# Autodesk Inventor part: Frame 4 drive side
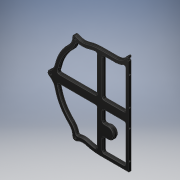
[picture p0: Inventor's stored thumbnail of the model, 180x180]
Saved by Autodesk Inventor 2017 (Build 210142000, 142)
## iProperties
Created: 2016-06
Part Number: Frame 4 drive side
Material: Generic
Document SubType Name: Modeling
Designer: Stan
Density: 1 g/cm^3
Appearance: Glossy - Black
Author: Stan
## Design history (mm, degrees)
sketch "Sketch1"
  geometry: L1 (9.525, 88.9)-(33.07, 88.9); L2 (0, -98.425)-(60.566, -98.425); L3 (9.525, -88.9)-(51.041, -88.9); L4 (6.35, 85.725)-(6.35, 12.7); L5 (6.35, -63.063)-(6.35, -85.725); L6 (-6.35, 85.194)-(-6.35, 12.7); L7 (-6.35, -12.7)-(-6.35, -85.194); L8 (-85.613, -9.525)-(-9.525, -9.525); L9 (9.525, -9.525)-(51.041, -9.525); L10 (-85.613, 9.525)-(-9.525, 9.525); L11 (9.525, 9.525)-(51.041, 9.525); L12 (33.07, 98.425)-(0, 98.425); L13 (60.566, 114.3)-(60.566, 110.49); L14 (60.566, 105.41)-(60.566, -98.425); L15 (54.216, 90.23)-(54.216, 12.7); L16 (54.216, -12.7)-(54.216, -85.725); L17 (6.35, -31.313)-(6.35, -12.7); L18 (17.394, -34.488)-(9.525, -34.488); L19 (17.394, -59.888)-(9.525, -59.888); C1 r 3.175 at (0, 0); C2 r 2.54 at (-104.775, 0); C3 r 2.54 at (-52.387, -90.738); C4 r 2.54 at (-52.388, 90.738); C5 r 3.175 at (17.394, -47.188); A1 r 3.175 centre (9.525, -85.725) between (6.35, -85.725) and (9.525, -88.9); A2 r 3.175 centre (9.525, 85.725) between (9.525, 88.9) and (6.35, 85.725); A3 r 3.175 centre (-9.525, -12.7) between (-6.35, -12.7) and (-9.525, -9.525); A4 r 3.175 centre (9.525, -12.7) between (9.525, -9.525) and (6.35, -12.7); A5 r 3.175 centre (51.041, -12.7) between (54.216, -12.7) and (51.041, -9.525); A6 r 3.175 centre (-9.525, 12.7) between (-9.525, 9.525) and (-6.35, 12.7); A7 r 3.175 centre (9.525, 12.7) between (6.35, 12.7) and (9.525, 9.525); A8 r 3.175 centre (51.041, 12.7) between (51.041, 9.525) and (54.216, 12.7); A9 r 98.425 centre (0, 0) between (0, 98.425) and (-29.099, 94.025); A10 r 98.425 centre (0, 0) between (-66.878, 72.213) and (-95.978, 21.812); A11 r 98.425 centre (0, 0) between (-95.978, -21.812) and (-66.878, -72.213); A12 r 98.425 centre (0, 0) between (-29.099, -94.025) and (0, -98.425); A13 r 88.9 centre (0, 0) between (-9.878, 88.35) and (-26.283, 84.926); A14 r 3.175 centre (-9.525, 85.194) between (-6.35, 85.194) and (-9.878, 88.35); A15 r 88.9 centre (0, 0) between (-60.406, 65.225) and (-86.69, 19.701); A16 r 88.9 centre (0, 0) between (-86.69, -19.701) and (-60.406, -65.225); A17 r 88.9 centre (0, 0) between (-26.283, -84.926) and (-9.878, -88.35); A18 r 3.175 centre (-9.525, -85.194) between (-9.878, -88.35) and (-6.35, -85.194); A19 r 6.35 centre (-104.775, 0) between (-107.969, 5.488) and (-107.969, -5.488); A20 r 25.4 centre (-120.746, 27.441) between (-107.969, 5.488) and (-95.978, 21.812); A21 r 34.925 centre (-120.746, 27.441) between (-88.541, 13.928) and (-86.69, 19.701); A22 r 3.175 centre (-85.613, 12.7) between (-88.541, 13.928) and (-85.613, 9.525); A23 r 25.4 centre (-120.746, -27.441) between (-95.978, -21.812) and (-107.969, -5.488); A24 r 34.925 centre (-120.746, -27.441) between (-86.69, -19.701) and (-88.541, -13.928); A25 r 3.175 centre (-85.613, -12.7) between (-85.613, -9.525) and (-88.541, -13.928); A26 r 6.35 centre (-52.387, -90.738) between (-58.737, -90.76) and (-49.232, -96.248); A27 r 25.4 centre (-84.137, -90.849) between (-58.737, -90.76) and (-66.878, -72.213); A28 r 34.925 centre (-84.137, -90.849) between (-50.239, -82.443) and (-60.406, -65.225); A29 r 3.175 centre (-47.157, -81.679) between (-50.239, -82.443) and (-46.278, -84.73); A30 r 25.4 centre (-36.609, -118.29) between (-29.099, -94.025) and (-49.232, -96.248); A31 r 34.925 centre (-36.609, -118.29) between (-26.283, -84.926) and (-46.278, -84.73); A32 r 6.35 centre (-52.388, 90.738) between (-49.232, 96.248) and (-58.737, 90.76); A33 r 25.4 centre (-36.609, 118.29) between (-49.232, 96.248) and (-29.099, 94.025); A34 r 34.925 centre (-36.609, 118.29) between (-46.278, 84.73) and (-26.283, 84.926); A35 r 3.175 centre (-47.157, 81.679) between (-46.278, 84.73) and (-50.239, 82.443); A36 r 25.4 centre (-84.137, 90.849) between (-66.878, 72.213) and (-58.737, 90.76); A37 r 34.925 centre (-84.137, 90.849) between (-60.406, 65.225) and (-50.239, 82.443); A38 r 6.35 centre (60.566, 107.95) between (60.566, 114.3) and (55.067, 111.125); A39 r 2.54 centre (60.566, 107.95) between (60.566, 110.49) and (60.566, 105.41); A40 r 25.4 centre (33.07, 123.825) between (33.07, 98.425) and (55.067, 111.125); A41 r 34.925 centre (33.07, 123.825) between (33.07, 88.9) and (49.544, 93.029); A42 r 3.175 centre (51.041, 90.23) between (54.216, 90.23) and (49.544, 93.029); A43 r 3.175 centre (51.041, -85.725) between (51.041, -88.9) and (54.216, -85.725); A44 r 3.175 centre (9.525, -31.313) between (6.35, -31.313) and (9.525, -34.488); A45 r 3.175 centre (9.525, -63.063) between (9.525, -59.888) and (6.35, -63.063); A46 r 12.7 centre (17.394, -47.188) between (17.394, -59.888) and (17.394, -34.488); 1 further point
  constraints: 92 point on circle, 51 centre point, 38 end point
  dimensions: "d17" = 6.35 diameter of C1; "d18" = 6.35 diameter of C5
extrude "Extrusion1" new body sketch "Sketch1" distance "d0" = 6.35; taper "d1" = 0 deg
fillet "Fillet1" dims "d2" = 1.5875
sketch "Sketch2"
  geometry: L1 (0, 0)-(0, 203.835) reference; C1 r 1.587 at (-3.175, 79.375); C2 r 1.587 at (-3.175, 117.475); C3 r 1.587 at (-3.175, 177.8); C4 r 1.587 at (-3.175, 19.05); 3 further points
  constraints: 4 centre point
  dimensions: "d3" = 9.525 vertical distance of C1.centre point (0, 88.9); "d4" = 9.525 vertical distance of C2.centre point (0, 107.95); "d5" = 60.325 distance of C3.centre C2.centre; "d6" = 60.325 distance of C4.centre C1.centre; "d7" = 3.175 distance from line of L1 C2.centre; "d8" = 3.175 distance from line of L1 C3.centre; "d9" = 3.175 distance from line of L1 C1.centre; "d10" = 3.175 distance from line of L1 C4.centre; "d11" = 3.175 diameter of C4; "d12" = 3.175 diameter of C1; "d13" = 3.175 diameter of C2; "d14" = 3.175 diameter of C3
extrude "Extrusion2" cut sketch "Sketch2" distance "d15" = 6.35; taper "d16" = 0 deg
sketch "Sketch3"
  geometry: C1 r 3.175 at (0, 0); 1 further point
  constraints: 1 centre point, 1 coincident
extrude "Extrusion3" join sketch "Sketch3" distance "d19" = 3.175; taper "d20" = 0 deg
sketch "Sketch7"
  geometry: C1 r 3.175 at (-17.394, -47.188) reference; C2 r 3.175 at (-17.394, -47.188); C3 r 11.112 at (-17.394, -47.188); 1 further point
  constraints: 2 centre point, 2 coincident
extrude "Extrusion5" join sketch "Sketch7" distance "d33" = 3.175; taper "d34" = 0 deg
sketch "Sketch8"
  geometry: C1 r 3.175 at (17.394, -47.188) reference; C2 r 3.175 at (17.394, -47.188); 1 further point
  constraints: 1 centre point, 1 coincident
extrude "Extrusion6" join sketch "Sketch8" distance "d35" = 1.5875; taper "d36" = 0 deg
body "Solid1"
